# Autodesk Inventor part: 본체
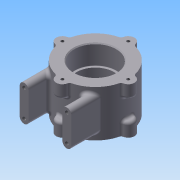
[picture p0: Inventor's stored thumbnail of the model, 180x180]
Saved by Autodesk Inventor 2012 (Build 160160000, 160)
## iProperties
Created: 2015-03
Part Number: 본체
Material: 알루미늄-6061
Document SubType Name: Modeling
Designer: net
Density: 2.71 g/cm^3
Mass: 438.468 g
Surface Area: 321.729 cm^2
Volume: 161.796 cm^3
Author: net
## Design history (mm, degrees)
sketch "스케치1"
  geometry: C1 r 37 at (0, 0); 1 further point
  constraints: 1 centre point, 1 coincident
  dimensions: "d0" = 74 diameter of C1
extrude "돌출1" new body sketch "스케치1" distance "d1" = 52; taper "d2" = 0 deg
node "작업 평면1"
sketch "스케치2"
  geometry: L1 (-29, 6)-(-19, 6); L2 (-19, 6)-(-19, 46); L3 (-19, 46)-(-29, 46); L4 (-29, 46)-(-29, 6); L5 (-37, 0)-(-37, 52) reference; L6 (29, 6)-(19, 6); L7 (19, 6)-(19, 46); L8 (19, 46)-(29, 46); L9 (29, 46)-(29, 6); 1 further point
  constraints: 16 end point, 2 parallel, 1 horizontal, 1 perpendicular
  dimensions: "d4" = 40 distance of L3.end L1.start; "d6" = 10 distance of L1.start L1.end
extrude "돌출2" join sketch "스케치2" stored distance "d8" = 52; taper "d9" = 0 deg
fillet "모깎기1" dims "d10" = 5
fillet "모깎기2" dims "d11" = 3
sketch "스케치4"
  geometry: L1 (-7, 37)-(-7, 36.332); L2 (7, 37)-(7, 36.332); A1 r 37 centre (0, 0) between (0, 37) and (-7, 36.332) reference; A2 r 7 centre (0, 37) between (7, 37) and (-7, 37)
  constraints: 5 point on circle, 4 end point, 1 centre point, 1 tangent, 1 vertical
extrude "돌출4" join sketch "스케치4" distance "d20" = 15; taper "d21" = 0 deg
fillet "모깎기3" dims "d22" = 3
sketch "스케치5"
  geometry: C1 r 7 at (0, 37); 1 further point
  constraints: 1 centre point, 1 vertical alignment, 1 other
  dimensions: "d26" = 14 diameter of C1
extrude "돌출5" join sketch "스케치5" distance "d27" = 15; taper "d28" = 0 deg
fillet "모깎기4" dims "d29" = 3
hole "구멍1" diameter "d32" = 4.134; stored, may be unused: countersink angle "d36" = 90 deg, drill point angle "d38" = 118 deg; dims "d30" = 10, "d31" = 10, "d33" = 6, "d34" = 4, "d35" = 2, "d37" = 8
hole "구멍2" diameter "d41" = 4.134; stored, may be unused: countersink angle "d45" = 90 deg, drill point angle "d47" = 118 deg; dims "d39" = 10, "d40" = 10, "d42" = 6, "d43" = 4, "d44" = 2, "d46" = 8
hole "구멍3" diameter "d50" = 4.134; stored, may be unused: countersink angle "d54" = 90 deg, drill point angle "d56" = 118 deg; dims "d48" = 10, "d49" = 10, "d51" = 6, "d52" = 4, "d53" = 2, "d55" = 8
hole "구멍4" diameter "d59" = 4.134; stored, may be unused: countersink angle "d63" = 90 deg, drill point angle "d65" = 118 deg; dims "d57" = 10, "d58" = 10, "d60" = 6, "d61" = 4, "d62" = 2, "d64" = 8
hole "구멍5" diameter "d71" = 3.242; stored, may be unused: countersink angle "d75" = 90 deg, drill point angle "d77" = 118 deg; dims "d69" = 10, "d70" = 10, "d72" = 8, "d73" = 4, "d74" = 2, "d76" = 11
hole "구멍6" diameter "d83" = 3.242; stored, may be unused: countersink angle "d87" = 90 deg, drill point angle "d89" = 118 deg; dims "d81" = 10, "d82" = 10, "d84" = 8, "d85" = 4, "d86" = 2, "d88" = 11
hole "구멍7" diameter "d95" = 42; stored, may be unused: countersink angle "d99" = 90 deg, drill point angle "d101" = 118 deg; dims "d93" = 10, "d94" = 10, "d96" = 8, "d97" = 47, "d98" = 22, "d100" = 11
hole "구멍8" diameter "d104" = 47; stored, may be unused: countersink angle "d108" = 90 deg, drill point angle "d110" = 0 deg; dims "d105" = 8, "d106" = 47, "d107" = 22, "d109" = 22, "d131" = 10, "d132" = 10
fillet "모깎기5" dims "d111" = 0.3
chamfer "모따기1" distance "d112" = 1; stored, may be unused: second distance "d113" = 2, angle "d114" = 45 deg
chamfer "모따기2" distance "d115" = 1; stored, may be unused: second distance "d116" = 2, angle "d117" = 45 deg
node "작업 평면9"
sketch "스케치12"
  geometry: 2 further points
  constraints: 1 other
  dimensions: "d127" = 0 horizontal distance of point (0, -52) point (0, -26); "d128" = 26 distance of point (0, -26) point (0, -52)
feature "엠보싱2" sketch "스케치12" dims "d1" = 52, "d10" = 5, "d129" = 0.5, "d130" = 0
node "솔리드1"
pattern_circular "원형 패턴1" dims angle "d24" = 360 deg
pattern_circular "원형 패턴2" dims angle "d67" = 360 deg
pattern_circular "원형 패턴3" dims angle "d79" = 360 deg
pattern_circular "원형 패턴4" dims angle "d91" = 360 deg
other parameters: "d3" = -56, "d12" = 15, "d14" = 7, "d18" = 14, "d19" = 14
